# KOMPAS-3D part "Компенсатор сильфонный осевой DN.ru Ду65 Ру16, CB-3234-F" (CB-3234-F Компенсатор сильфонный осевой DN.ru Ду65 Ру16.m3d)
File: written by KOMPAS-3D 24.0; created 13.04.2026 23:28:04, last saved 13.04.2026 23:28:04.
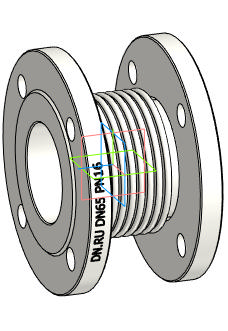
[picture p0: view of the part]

Document properties: Автор: DN.RU; Полное имя файла: D:\PROJECT CAD\DN.RU\...198(ACTUALE). CB-3234-F Компенсатор сильфонный осевой DN.ru\Исходники\DN65\CB-3234-F Компенсатор сильфонный осевой DN.ru Ду65 Ру16.m3d

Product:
- Body: Твердое тело1  | qty 1
    Масса: 7.336291
- Part/product: Компенсатор сильфонный осевой DN.ru Ду65 Ру16  | designation CB-3234-F
    Масса: 6
    Раздел спецификации: Прочие изделия
    Комментарий: D140-02114
    Примечание: D140-02114
    additional columns: Типовые

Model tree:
1. Твердое тело1  (labels: Твердое тело1)

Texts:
  CB-3234-F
